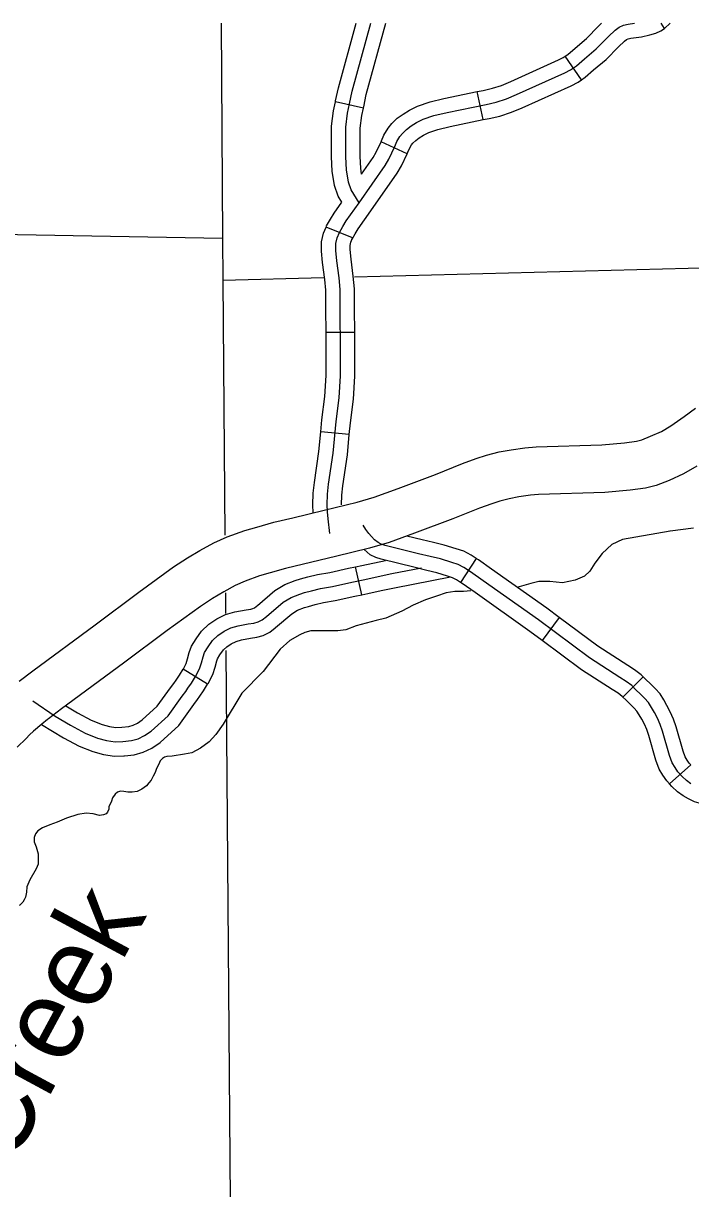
# Model space of a CAD drawing. Extents: x -3711 to 825, y -151 to 1050.
# Drawn here: x -2612.2 to -2573.1, y 443.6 to 512 of the extents above; entities that cross this region are included whole.
import ezdxf

# ---------------------------------------------------------------- set-up
doc = ezdxf.new("R2010")
doc.units = 0
for name, color, linetype in [('Level 10', 7, 'Continuous'), ('Level 32', 7, 'Continuous'), ('Level 35', 7, 'Continuous'), ('Level 4', 7, 'Continuous'), ('Level 45', 7, 'Continuous'), ('Level 46', 7, 'Continuous'), ('Level 5', 7, 'Continuous')]:
    doc.layers.add(name, color=color, linetype=linetype)

msp = doc.modelspace()

# ---------------------------------------------------------------- linework, layer by layer
at = {"layer": 'Level 10'}
for points in [[(-2612.418, 473.396), (-2611.63, 473.999), (-2607.975, 476.697), (-2605.413, 478.609), (-2603.382, 480.087), (-2602.558, 480.62), (-2601.823, 481.058), (-2601.016, 481.502), (-2600.221, 481.858), (-2599.192, 482.224), (-2598.495, 482.43), (-2597.501, 482.714), (-2596.385, 482.97), (-2594.538, 483.416), (-2592.614, 483.888), (-2591.608, 484.185), (-2590.207, 484.689), (-2588.014, 485.518), (-2586.437, 486.158), (-2585.624, 486.445), (-2585.018, 486.647), (-2584.285, 486.831), (-2583.585, 486.956), (-2582.771, 487.079), (-2582.12, 487.131), (-2578.258, 487.244), (-2576.932, 487.373), (-2576.235, 487.473), (-2575.918, 487.548), (-2575.405, 487.75), (-2574.761, 488.037), (-2574.221, 488.359), (-2573.438, 488.91), (-2572.764, 489.405)], [(-2572.696, 486.006), (-2573.468, 485.546), (-2574.32, 485.165), (-2575.076, 484.868), (-2575.711, 484.717), (-2576.599, 484.59), (-2578.082, 484.446), (-2581.967, 484.333), (-2582.448, 484.294), (-2583.129, 484.191), (-2583.698, 484.089), (-2584.233, 483.955), (-2584.714, 483.795), (-2585.442, 483.538), (-2586.991, 482.909), (-2589.238, 482.06), (-2590.736, 481.521), (-2591.882, 481.182), (-2593.876, 480.693), (-2595.744, 480.243), (-2596.803, 480), (-2597.712, 479.74), (-2598.324, 479.558), (-2599.177, 479.255), (-2599.766, 478.991), (-2600.431, 478.626), (-2601.079, 478.24), (-2601.795, 477.776), (-2603.751, 476.353), (-2606.306, 474.447), (-2609.946, 471.759), (-2610.698, 471.184), (-2610.758, 471.137), (-2611.094, 470.871), (-2611.581, 470.448), (-2611.816, 470.236), (-2612.022, 470.034), (-2612.534, 469.513)]]:
    msp.add_lwpolyline(points, dxfattribs=at)
at = {"layer": 'Level 32'}
for p, q in [((-2574.585, 511.669), (-2574.776, 511.974)), ((-2579.455, 508.667), (-2580.403, 510.055)), ((-2585.217, 506.323), (-2585.562, 507.969)), ((-2592.241, 506.997), (-2593.881, 507.367)), ((-2589.677, 504.311), (-2591.203, 505.015)), ((-2592.873, 499.384), (-2594.428, 500.024)), ((-2592.748, 493.844), (-2594.43, 493.83)), ((-2593.069, 487.857), (-2594.743, 488.015)), ((-2585.627, 480.585), (-2586.549, 479.179)), ((-2580.764, 477.126), (-2581.767, 475.777)), ((-2575.835, 473.644), (-2577.024, 472.456)), ((-2573.052, 468.491), (-2574.302, 467.367))]:
    msp.add_line(p, q, dxfattribs=at)
for points in [[(-2594.207, 482.054), (-2594.31, 482.903), (-2594.351, 483.329), (-2594.362, 483.725), (-2594.343, 484.364), (-2594.278, 484.943), (-2594.016, 486.766), (-2593.841, 488.622), (-2593.667, 490.009), (-2593.579, 491.298), (-2593.579, 492.739), (-2593.601, 495.207), (-2593.601, 496.364), (-2593.667, 497.041), (-2593.798, 498.046), (-2593.863, 498.657), (-2593.863, 499.05), (-2593.776, 499.4), (-2593.65, 499.704), (-2593.443, 500.053), (-2593.252, 500.382), (-2592.498, 501.449), (-2590.97, 503.64), (-2590.742, 504.008), (-2590.404, 504.741), (-2590.284, 505.036), (-2590.11, 505.34), (-2589.957, 505.514), (-2589.717, 505.755), (-2589.433, 505.951), (-2589.128, 506.148), (-2588.735, 506.344), (-2588.102, 506.563), (-2587.338, 506.737), (-2585.047, 507.218), (-2584.458, 507.349), (-2583.847, 507.545), (-2583.268, 507.794), (-2580.425, 509.07), (-2580.093, 509.249), (-2579.749, 509.484), (-2579.286, 509.882), (-2578.587, 510.472), (-2577.87, 511.2), (-2577.476, 511.573), (-2577.248, 511.74), (-2576.999, 511.864), (-2576.708, 511.927), (-2576.354, 511.974)], [(-2593.881, 507.367), (-2593.868, 507.425), (-2593.707, 508.192), (-2592.671, 511.974)], [(-2592.498, 501.449), (-2592.96, 502.21), (-2593.124, 502.666), (-2593.237, 503.387), (-2593.272, 504.152), (-2593.272, 505.074), (-2593.263, 505.884), (-2593.168, 506.708), (-2593.046, 507.247), (-2592.89, 507.994), (-2591.799, 511.974)], [(-2592.241, 506.997), (-2592.225, 507.068), (-2592.072, 507.797), (-2590.927, 511.974)], [(-2580.403, 510.055), (-2580.262, 510.152), (-2579.831, 510.522), (-2579.159, 511.089), (-2578.459, 511.8), (-2578.276, 511.974)], [(-2579.455, 508.667), (-2579.236, 508.816), (-2578.741, 509.242), (-2578.016, 509.854), (-2577.282, 510.599), (-2576.937, 510.926), (-2576.809, 511.019), (-2576.718, 511.065), (-2576.564, 511.098), (-2575.927, 511.183), (-2575.452, 511.301), (-2575.092, 511.405), (-2574.796, 511.536), (-2574.585, 511.669)], [(-2574.586, 511.668), (-2574.584, 511.67)], [(-2585.562, 507.969), (-2585.224, 508.04), (-2584.678, 508.161), (-2584.142, 508.333), (-2583.606, 508.564), (-2580.797, 509.824), (-2580.531, 509.968), (-2580.403, 510.055)], [(-2585.217, 506.323), (-2584.869, 506.396), (-2584.237, 506.537), (-2583.551, 506.757), (-2582.93, 507.024), (-2580.052, 508.315), (-2579.655, 508.53), (-2579.455, 508.667)], [(-2591.203, 505.015), (-2591.175, 505.076), (-2591.041, 505.405), (-2590.797, 505.83), (-2590.571, 506.089), (-2590.258, 506.402), (-2589.9, 506.65), (-2589.544, 506.879), (-2589.061, 507.121), (-2588.333, 507.372), (-2587.518, 507.559), (-2585.562, 507.969)], [(-2593.503, 501.484), (-2593.722, 501.845), (-2593.943, 502.456), (-2594.075, 503.303), (-2594.113, 504.133), (-2594.113, 505.079), (-2594.103, 505.937), (-2593.998, 506.849), (-2593.881, 507.367)], [(-2592.347, 503.135), (-2592.4, 503.471), (-2592.432, 504.171), (-2592.432, 505.069), (-2592.422, 505.831), (-2592.338, 506.567), (-2592.241, 506.997)], [(-2589.677, 504.311), (-2589.633, 504.407), (-2589.527, 504.666), (-2589.422, 504.849), (-2589.342, 504.94), (-2589.176, 505.107), (-2588.966, 505.252), (-2588.711, 505.416), (-2588.408, 505.568), (-2587.87, 505.753), (-2587.158, 505.916), (-2585.217, 506.323)], [(-2592.347, 503.135), (-2591.673, 504.102), (-2591.484, 504.407), (-2591.203, 505.015)], [(-2592.905, 499.313), (-2592.719, 499.627), (-2592.544, 499.928), (-2591.81, 500.966), (-2590.268, 503.178), (-2590.001, 503.608), (-2589.677, 504.311)], [(-2594.414, 500.056), (-2594.395, 500.096), (-2594.168, 500.479), (-2593.96, 500.837), (-2593.503, 501.484)], [(-2594.43, 493.83), (-2594.442, 495.203), (-2594.442, 496.324), (-2594.502, 496.946), (-2594.632, 497.947), (-2594.704, 498.612), (-2594.704, 499.154), (-2594.576, 499.663), (-2594.428, 500.024)], [(-2592.748, 493.844), (-2592.761, 495.21), (-2592.761, 496.405), (-2592.831, 497.136), (-2592.963, 498.145), (-2593.022, 498.702), (-2593.022, 498.947), (-2592.975, 499.137), (-2592.873, 499.384)], [(-2594.743, 488.015), (-2594.677, 488.714), (-2594.504, 490.09), (-2594.42, 491.326), (-2594.42, 492.735), (-2594.43, 493.83)], [(-2593.069, 487.857), (-2593.006, 488.531), (-2592.83, 489.928), (-2592.739, 491.269), (-2592.739, 492.743), (-2592.748, 493.844)], [(-2595.19, 483.258), (-2595.202, 483.726), (-2595.182, 484.423), (-2595.112, 485.05), (-2594.851, 486.865), (-2594.743, 488.015)], [(-2593.521, 483.724), (-2593.504, 484.304), (-2593.444, 484.836), (-2593.181, 486.667), (-2593.069, 487.857)], [(-2581.983, 476.985), (-2585.211, 479.272), (-2585.969, 479.804), (-2586.354, 480.057), (-2586.686, 480.229), (-2587.058, 480.349), (-2587.722, 480.562), (-2588.32, 480.695), (-2589.002, 480.863), (-2590.964, 481.346), (-2591.196, 481.424), (-2591.378, 481.515), (-2591.585, 481.683), (-2591.774, 481.878), (-2591.917, 482.047), (-2592.092, 482.281), (-2592.248, 482.535)], [(-2585.627, 480.585), (-2585.928, 480.783), (-2586.361, 481.008), (-2586.801, 481.15), (-2587.503, 481.374), (-2588.128, 481.513), (-2588.801, 481.679), (-2589.689, 481.898)], [(-2586.549, 479.179), (-2586.779, 479.33), (-2587.011, 479.451), (-2587.315, 479.549), (-2587.942, 479.75), (-2588.512, 479.876), (-2589.204, 480.047), (-2591.198, 480.538), (-2591.518, 480.645), (-2591.836, 480.804), (-2592.204, 481.103)], [(-2580.764, 477.126), (-2581.489, 477.665), (-2584.727, 479.959), (-2585.496, 480.5), (-2585.627, 480.585)], [(-2581.767, 475.777), (-2582.476, 476.305), (-2585.696, 478.585), (-2586.441, 479.108), (-2586.549, 479.179)], [(-2575.835, 473.644), (-2575.956, 473.766), (-2576.347, 474.059), (-2576.745, 474.315), (-2578.501, 475.443), (-2580.764, 477.126)], [(-2573.041, 467.372), (-2573.293, 467.558), (-2573.559, 467.797), (-2573.798, 468.063), (-2573.971, 468.316), (-2574.13, 468.595), (-2574.29, 469.021), (-2574.701, 470.457), (-2574.848, 470.855), (-2575.007, 471.228), (-2575.18, 471.56), (-2575.352, 471.853), (-2575.525, 472.132), (-2575.751, 472.385), (-2575.99, 472.624), (-2576.269, 472.89), (-2576.508, 473.129), (-2576.827, 473.368), (-2577.199, 473.608), (-2578.98, 474.751), (-2581.983, 476.985)], [(-2577.024, 472.456), (-2577.061, 472.493), (-2577.308, 472.678), (-2577.654, 472.901), (-2579.458, 474.06), (-2581.767, 475.777)], [(-2573.052, 468.491), (-2573.136, 468.584), (-2573.258, 468.762), (-2573.367, 468.953), (-2573.491, 469.284), (-2573.902, 470.717), (-2574.066, 471.166), (-2574.247, 471.587), (-2574.444, 471.968), (-2574.633, 472.288), (-2574.849, 472.637), (-2575.14, 472.962), (-2575.403, 473.225), (-2575.682, 473.491), (-2575.835, 473.644)], [(-2574.302, 467.367), (-2574.46, 467.543), (-2574.684, 467.869), (-2574.894, 468.237), (-2575.088, 468.757), (-2575.501, 470.196), (-2575.629, 470.545), (-2575.767, 470.868), (-2575.915, 471.152), (-2576.072, 471.418), (-2576.201, 471.627), (-2576.362, 471.807), (-2576.578, 472.022), (-2576.857, 472.288), (-2577.024, 472.456)], [(-2568.043, 466.823), (-2568.403, 466.779), (-2568.686, 466.732), (-2568.874, 466.692), (-2569.159, 466.597), (-2570.02, 466.337), (-2570.464, 466.219), (-2570.897, 466.138), (-2571.306, 466.106), (-2571.626, 466.106), (-2572.025, 466.138), (-2572.425, 466.202), (-2572.825, 466.302), (-2573.173, 466.485), (-2573.495, 466.662), (-2573.825, 466.906), (-2574.154, 467.202), (-2574.303, 467.367)]]:
    msp.add_lwpolyline(points, dxfattribs=at)
at = {"layer": 'Level 35'}
for points in [[(-2574.249, 482.179), (-2577.053, 481.701), (-2577.681, 481.404), (-2578.244, 480.874), (-2578.674, 480.311)], [(-2574.249, 482.179), (-2574.273, 482.178)], [(-2572.885, 482.354), (-2574.249, 482.179)], [(-2578.674, 480.311), (-2578.971, 479.848), (-2579.269, 479.55), (-2579.831, 479.318), (-2580.563, 479.151), (-2581.317, 479.238), (-2581.956, 479.238), (-2582.42, 479.121), (-2582.826, 479.005), (-2583.24, 478.891)], [(-2585.944, 478.68), (-2586.366, 478.657), (-2586.888, 478.657), (-2587.381, 478.57), (-2587.961, 478.367), (-2588.6, 478.163), (-2589.325, 477.844), (-2589.992, 477.496), (-2590.921, 477.089), (-2591.501, 476.944), (-2592.661, 476.625), (-2593.271, 476.392), (-2593.735, 476.334), (-2593.938, 476.334), (-2594.286, 476.334), (-2594.692, 476.334), (-2595.098, 476.334), (-2595.33, 476.334), (-2595.679, 476.247), (-2595.969, 476.102), (-2596.549, 475.783), (-2597.129, 475.26), (-2598.116, 473.954), (-2599.363, 472.676), (-2600.466, 470.876), (-2600.901, 470.266), (-2601.278, 469.831), (-2601.8, 469.453), (-2602.293, 469.192), (-2602.729, 469.105), (-2603.454, 468.989), (-2603.773, 468.973), (-2603.906, 468.94), (-2604.023, 468.857), (-2604.156, 468.707), (-2604.239, 468.524), (-2604.372, 468.274), (-2604.455, 468.041), (-2604.572, 467.824), (-2604.688, 467.591), (-2604.822, 467.424), (-2604.955, 467.258), (-2605.238, 467.058), (-2605.504, 466.925), (-2605.804, 466.875), (-2606.053, 466.875), (-2606.286, 466.925), (-2606.486, 466.941), (-2606.652, 466.875), (-2606.802, 466.758), (-2606.952, 466.542), (-2607.019, 466.358), (-2607.168, 466.025), (-2607.168, 465.875), (-2607.235, 465.709), (-2607.318, 465.609), (-2607.485, 465.542), (-2607.718, 465.509), (-2608.086, 465.598), (-2608.493, 465.644), (-2608.991, 465.576), (-2609.648, 465.349), (-2610.191, 465.122)], [(-2610.191, 465.122), (-2610.622, 464.964), (-2611.052, 464.783), (-2611.324, 464.601), (-2611.459, 464.443), (-2611.534, 464.223), (-2611.534, 463.957), (-2611.434, 463.674), (-2611.317, 463.257), (-2611.301, 462.991), (-2611.301, 462.658), (-2611.434, 462.375), (-2611.8, 461.742), (-2611.966, 461.325), (-2612, 461.009), (-2612.05, 460.726), (-2612.133, 460.559), (-2612.199, 460.426), (-2612.299, 460.326), (-2612.382, 460.259), (-2612.432, 460.226)]]:
    msp.add_lwpolyline(points, dxfattribs=at)
at = {"layer": 'Level 4'}
for points in [[(-2600.576, 511.974), (-2600.494, 499.375), (-2600.475, 496.909), (-2600.359, 481.951)], [(-2600.333, 478.574), (-2600.324, 477.355)], [(-2600.307, 475.197), (-2600.039, 440.417)]]:
    msp.add_lwpolyline(points, dxfattribs=at)
at = {"layer": 'Level 45'}
for p, q in [((-2592.342, 478.456), (-2592.695, 480.1)), ((-2601.378, 473.206), (-2602.81, 474.086))]:
    msp.add_line(p, q, dxfattribs=at)
for points in [[(-2611.626, 472.236), (-2610.307, 471.345), (-2609.413, 470.802), (-2608.548, 470.333), (-2607.83, 470.054), (-2607.302, 469.907), (-2606.789, 469.834), (-2606.341, 469.854), (-2605.844, 469.901), (-2605.449, 470.014), (-2605.065, 470.193), (-2604.68, 470.456), (-2603.696, 471.359), (-2602.859, 472.503), (-2602.661, 472.781), (-2602.53, 472.978), (-2602.318, 473.281), (-2602.084, 473.662), (-2601.855, 474.109), (-2601.742, 474.457), (-2601.644, 474.821), (-2601.556, 475.071), (-2601.351, 475.408), (-2601.087, 475.775), (-2600.779, 476.068), (-2600.413, 476.317), (-2600.017, 476.508), (-2599.592, 476.64), (-2598.991, 476.743), (-2598.669, 476.787), (-2598.419, 476.86), (-2598.185, 476.978), (-2597.921, 477.183), (-2596.939, 478.019), (-2596.468, 478.305), (-2595.97, 478.499), (-2595.693, 478.582), (-2595.279, 478.692), (-2594.753, 478.831), (-2594.061, 478.941), (-2592.927, 479.191), (-2592.153, 479.357), (-2591.375, 479.523), (-2590.583, 479.695), (-2588.84, 480.038)], [(-2598.45, 477.836), (-2597.433, 478.703), (-2596.841, 479.062), (-2596.244, 479.294), (-2595.923, 479.39), (-2595.494, 479.505), (-2594.927, 479.654), (-2594.218, 479.768), (-2593.106, 480.012), (-2592.695, 480.1)], [(-2592.695, 480.1), (-2592.329, 480.179), (-2590.943, 480.475)], [(-2592.342, 478.456), (-2591.977, 478.535), (-2591.198, 478.702), (-2590.413, 478.872), (-2587.137, 479.516)], [(-2602.817, 474.075), (-2602.634, 474.433), (-2602.548, 474.696), (-2602.447, 475.071), (-2602.32, 475.433), (-2602.052, 475.873), (-2601.724, 476.329), (-2601.309, 476.724), (-2600.834, 477.048), (-2600.326, 477.292), (-2599.788, 477.459), (-2599.119, 477.574), (-2598.845, 477.611), (-2598.729, 477.645), (-2598.635, 477.692), (-2598.439, 477.845)], [(-2597.409, 476.516), (-2597.392, 476.53), (-2596.445, 477.335), (-2596.095, 477.548), (-2595.696, 477.703), (-2595.464, 477.773), (-2595.063, 477.88), (-2594.579, 478.007), (-2593.905, 478.115), (-2592.749, 478.369), (-2592.342, 478.456)], [(-2601.378, 473.206), (-2601.351, 473.25), (-2601.076, 473.786), (-2600.936, 474.218), (-2600.841, 474.572), (-2600.792, 474.708), (-2600.65, 474.943), (-2600.45, 475.22), (-2600.249, 475.412), (-2599.992, 475.587), (-2599.708, 475.724), (-2599.396, 475.821), (-2598.863, 475.912), (-2598.492, 475.963), (-2598.11, 476.075), (-2597.734, 476.263), (-2597.406, 476.518)], [(-2606.409, 470.692), (-2606, 470.731), (-2605.743, 470.804), (-2605.481, 470.926), (-2605.204, 471.115), (-2604.326, 471.923), (-2603.541, 472.995), (-2603.354, 473.258), (-2603.224, 473.452), (-2603.021, 473.742), (-2602.81, 474.086)], [(-2606.251, 469.019), (-2605.687, 469.072), (-2605.155, 469.224), (-2604.648, 469.459), (-2604.155, 469.796), (-2603.067, 470.796), (-2602.177, 472.011), (-2601.969, 472.305), (-2601.835, 472.505), (-2601.615, 472.82), (-2601.378, 473.206)], [(-2609.686, 471.951), (-2608.994, 471.531), (-2608.194, 471.097), (-2607.564, 470.853), (-2607.129, 470.732), (-2606.748, 470.677), (-2606.4, 470.693), (-2606.409, 470.692)], [(-2611.116, 470.852), (-2609.832, 470.073), (-2608.902, 469.568), (-2608.095, 469.255), (-2607.475, 469.083), (-2606.83, 468.991), (-2606.282, 469.016), (-2606.251, 469.019)]]:
    msp.add_lwpolyline(points, dxfattribs=at)
at = {"layer": 'Level 46'}
msp.add_lwpolyline([(-2574.584, 511.67), (-2574.25, 511.974)], dxfattribs=at)
at = {"layer": 'Level 5'}
for points in [[(-2619.104, 499.703), (-2600.494, 499.375)], [(-2592.761, 497.109), (-2565.678, 497.813)], [(-2600.475, 496.909), (-2594.552, 497.063)]]:
    msp.add_lwpolyline(points, dxfattribs=at)

# ---------------------------------------------------------------- texts
at = {"layer": 'Level 35'}
msp.add_text('Creek', height=4.7343, rotation=61.62494, dxfattribs=at).set_placement((-2612.952, 444.77))

doc.saveas('drawing.dxf')
